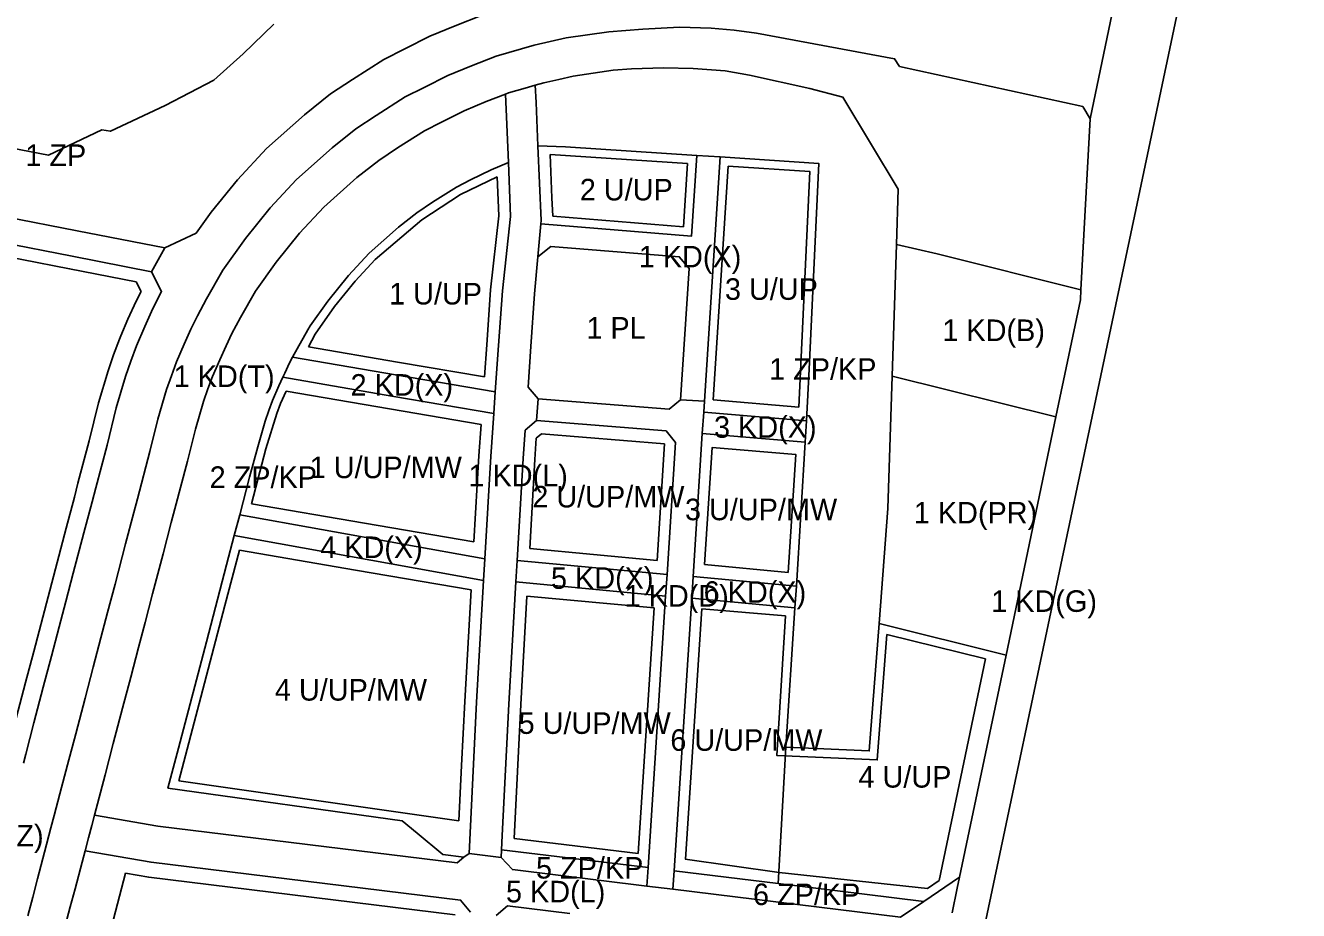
# Model space of a CAD drawing. Extents: x 7424258 to 7426021, y 5551671 to 5553193.
# Drawn here: x 7425401 to 7425992, y 5552263 to 5552673 of the extents above; entities that cross this region are included whole.
import ezdxf

# ---------------------------------------------------------------- set-up
doc = ezdxf.new("R2010")
doc.units = 0
for name, color, linetype in [('linie_rozgraniczajace', 7, 'Continuous'), ('linie_zabudowy_nieprzekraczalne', 7, 'Continuous'), ('linie_zabudowy_obowiazujace', 7, 'Continuous'), ('oznaczenia_przeznaczen', 7, 'Continuous')]:
    doc.layers.add(name, color=color, linetype=linetype)

msp = doc.modelspace()

# ---------------------------------------------------------------- linework, layer by layer
at = {"layer": 'linie_rozgraniczajace'}
for points in [[(7425991.56, 5552946.2), (7425916.04, 5552588.04), (7425881.23, 5552423.32), (7425846.58, 5552258.58)], [(7425516.29, 5552674.09), (7425501.98, 5552660.41), (7425488.46, 5552648.19), (7425465.82, 5552636.34), (7425440.5, 5552624.42), (7425436.43, 5552625.15), (7425411.75, 5552613.27), (7425339.38, 5552627.28), (7425321.43, 5552647.09), (7425251.22, 5552724.52)], [(7425906.69, 5552686.84), (7425894.92, 5552630.26), (7425891.45, 5552635.89), (7425806.54, 5552654.5), (7425804.19, 5552658.05), (7425740.11, 5552669.93), (7425729.85, 5552671.28), (7425719.09, 5552672.17), (7425704.44, 5552672.69), (7425687.35, 5552671.82), (7425671.67, 5552670.61), (7425651.9, 5552667.68), (7425637.06, 5552664.4), (7425619.34, 5552659.27), (7425608.01, 5552654.84), (7425597.01, 5552650.26), (7425585.94, 5552644.72), (7425577.21, 5552640.33), (7425563.73, 5552631.74), (7425554.37, 5552625.51), (7425543.27, 5552616.76), (7425526.81, 5552602.12), (7425514.58, 5552588.87), (7425503.09, 5552574.71), (7425492.57, 5552560.02), (7425485.04, 5552546.67), (7425480.8, 5552538.84), (7425477.8, 5552532.56), (7425474.68, 5552525.73), (7425471.14, 5552517.42), (7425468.75, 5552511.05), (7425466.52, 5552504.57), (7425462.5, 5552490.93), (7425458.73, 5552475.88), (7425452.97, 5552453.86), (7425451.31, 5552447.53), (7425447.5, 5552433.03), (7425442.6, 5552414.41), (7425439.13, 5552401.23), (7425436.07, 5552389.53), (7425432.46, 5552375.83), (7425428.69, 5552361.48), (7425424.36, 5552345.01), (7425420.55, 5552330.49), (7425417.03, 5552317.12), (7425414.37, 5552306.98), (7425412.86, 5552301.29), (7425409.89, 5552289.99), (7425406.66, 5552277.68), (7425404.45, 5552269.24), (7425402.13, 5552260.45)], [(7425830.86, 5552261.88), (7425833.28, 5552273.38), (7425834.35, 5552278.52), (7425855.89, 5552381.38), (7425879.03, 5552491.92), (7425890.41, 5552546.24), (7425890.65, 5552550.86), (7425894.92, 5552630.26), (7425906.69, 5552686.84)], [(7425612.91, 5552678.24), (7425600.34, 5552673.3), (7425588.67, 5552668.46), (7425576.97, 5552662.59), (7425567.32, 5552657.74), (7425552.82, 5552648.5), (7425542.61, 5552641.71), (7425530.42, 5552632.09), (7425512.79, 5552616.41), (7425499.46, 5552601.97), (7425487.18, 5552586.84), (7425480.2, 5552577.11), (7425465.64, 5552570.34), (7425424.98, 5552578.29), (7425358.36, 5552591.28), (7425306.08, 5552601.31), (7425191.3, 5552623.7), (7425147.23, 5552632.41), (7425138.81, 5552645.48), (7425140.06, 5552650.56), (7425144.04, 5552663.41), (7425151.8, 5552674.07)], [(7425157.19, 5552680.03), (7425250.04, 5552661.6), (7425301.71, 5552651.12), (7425321.43, 5552647.09), (7425339.38, 5552627.28), (7425411.75, 5552613.27), (7425436.43, 5552625.15), (7425440.5, 5552624.42), (7425465.82, 5552636.34), (7425488.46, 5552648.19), (7425501.98, 5552660.41), (7425516.29, 5552674.09)], [(7425499.46, 5552601.97), (7425512.79, 5552616.41), (7425530.42, 5552632.09), (7425542.61, 5552641.71), (7425552.82, 5552648.5), (7425567.32, 5552657.74), (7425576.97, 5552662.59), (7425588.67, 5552668.46), (7425600.34, 5552673.3), (7425612.91, 5552678.24)], [(7425402.13, 5552260.45), (7425404.45, 5552269.24), (7425406.66, 5552277.68), (7425409.89, 5552289.99), (7425412.86, 5552301.29), (7425414.37, 5552306.98), (7425417.03, 5552317.12), (7425420.55, 5552330.49), (7425424.36, 5552345.01), (7425428.69, 5552361.48), (7425432.46, 5552375.83), (7425436.07, 5552389.53), (7425439.13, 5552401.23), (7425442.6, 5552414.41), (7425447.5, 5552433.03), (7425451.31, 5552447.53), (7425452.97, 5552453.86), (7425458.73, 5552475.88), (7425462.5, 5552490.93), (7425466.52, 5552504.57), (7425468.75, 5552511.05), (7425471.14, 5552517.42), (7425474.68, 5552525.73), (7425477.8, 5552532.56), (7425480.8, 5552538.84), (7425485.04, 5552546.67), (7425492.57, 5552560.02), (7425503.09, 5552574.71), (7425514.58, 5552588.87), (7425526.81, 5552602.12), (7425543.27, 5552616.76), (7425554.37, 5552625.51), (7425563.73, 5552631.74), (7425577.21, 5552640.33), (7425585.94, 5552644.72), (7425597.01, 5552650.26), (7425608.01, 5552654.84), (7425619.34, 5552659.27), (7425637.06, 5552664.4), (7425651.9, 5552667.68), (7425671.67, 5552670.61), (7425687.35, 5552671.82), (7425704.44, 5552672.69), (7425719.09, 5552672.17), (7425729.85, 5552671.28), (7425740.11, 5552669.93), (7425804.19, 5552658.05), (7425806.54, 5552654.5), (7425891.45, 5552635.89), (7425894.92, 5552630.26), (7425890.65, 5552550.86), (7425823.92, 5552567.51), (7425805.06, 5552571.87), (7425805.89, 5552597.52), (7425780.24, 5552640.21), (7425764.95, 5552644.18), (7425736.94, 5552650.37), (7425725.59, 5552652.38), (7425710.7, 5552653.54), (7425696.94, 5552653.88), (7425682.2, 5552653.37), (7425673.69, 5552652.71), (7425655.16, 5552649.97), (7425648.41, 5552648.47), (7425641.51, 5552646.94), (7425637.55, 5552645.8), (7425632.85, 5552644.45), (7425625.13, 5552642.22), (7425623.71, 5552641.66), (7425614.75, 5552638.15), (7425604.51, 5552633.89), (7425594.01, 5552628.62), (7425586.11, 5552624.66), (7425573.55, 5552616.66), (7425564.95, 5552610.93)], [(7425564.95, 5552610.93), (7425554.83, 5552602.96), (7425539.44, 5552589.26), (7425528.2, 5552577.09), (7425517.4, 5552563.78), (7425507.76, 5552550.33), (7425500.8, 5552537.98), (7425496.84, 5552530.66), (7425494.11, 5552524.95), (7425491.15, 5552518.46), (7425487.85, 5552510.72), (7425485.69, 5552504.97), (7425483.68, 5552499.1), (7425479.87, 5552486.2), (7425476.17, 5552471.42), (7425470.38, 5552449.29), (7425468.71, 5552442.95), (7425464.9, 5552428.47), (7425460.01, 5552409.83), (7425456.54, 5552396.65), (7425453.46, 5552384.96), (7425449.87, 5552371.26), (7425446.1, 5552356.91), (7425441.77, 5552340.43), (7425437.96, 5552325.92), (7425433.05, 5552307.27), (7425431.77, 5552302.42), (7425430.27, 5552296.71), (7425428.7, 5552290.74), (7425427.3, 5552285.41), (7425424.07, 5552273.1), (7425421.85, 5552264.67), (7425419.54, 5552255.88)], [(7425400.09, 5552331.38), (7425401.21, 5552335.58), (7425405.02, 5552350.1), (7425409.35, 5552366.57), (7425413.12, 5552380.92), (7425416.71, 5552394.62), (7425419.79, 5552406.31), (7425423.26, 5552419.5), (7425428.15, 5552438.12), (7425431.96, 5552452.61), (7425433.64, 5552458.98), (7425438.91, 5552478.79), (7425443.21, 5552496.2), (7425447.47, 5552510.65), (7425449.93, 5552517.8), (7425452.57, 5552524.86), (7425456.39, 5552533.8), (7425460.2, 5552542.16), (7425464.18, 5552550.15), (7425459.57, 5552559.28), (7425465.64, 5552570.34), (7425480.2, 5552577.11), (7425487.18, 5552586.84), (7425499.46, 5552601.97)], [(7425356.08, 5552579.5), (7425422.69, 5552566.52), (7425459.57, 5552559.28), (7425464.18, 5552550.15), (7425460.2, 5552542.16), (7425456.39, 5552533.8), (7425452.57, 5552524.86), (7425449.93, 5552517.8), (7425447.47, 5552510.65), (7425443.21, 5552496.2), (7425438.91, 5552478.79), (7425433.64, 5552458.98), (7425431.96, 5552452.61), (7425428.15, 5552438.12), (7425423.26, 5552419.5), (7425419.79, 5552406.31), (7425416.71, 5552394.62), (7425413.12, 5552380.92), (7425409.35, 5552366.57), (7425405.02, 5552350.1), (7425401.21, 5552335.58), (7425400.09, 5552331.38)], [(7425607.51, 5552262.2), (7425602.87, 5552267.8), (7425459.3, 5552285.38), (7425428.7, 5552290.74), (7425430.27, 5552296.71), (7425431.77, 5552302.42), (7425433.05, 5552307.27), (7425462.51, 5552302.11), (7425601.24, 5552285.12), (7425604.38, 5552287.76), (7425606.81, 5552289.46), (7425621.74, 5552287.61), (7425626.92, 5552281.98), (7425689.34, 5552274.33), (7425701.37, 5552272.89), (7425807, 5552259.94), (7425817.72, 5552267.22), (7425834.35, 5552278.52), (7425833.28, 5552273.38), (7425830.86, 5552261.88)], [(7425419.54, 5552255.88), (7425421.85, 5552264.67), (7425424.07, 5552273.1), (7425427.3, 5552285.41), (7425428.7, 5552290.74), (7425459.3, 5552285.38), (7425602.87, 5552267.8), (7425607.51, 5552262.2)], [(7425653.53, 5552261.6), (7425624.71, 5552265.13), (7425619.43, 5552260.74)], [(7425619.43, 5552260.74), (7425624.71, 5552265.13), (7425653.53, 5552261.6)]]:
    msp.add_lwpolyline(points, dxfattribs=at)
for points in [[(7425637.55, 5552645.8), (7425641.51, 5552646.94), (7425648.41, 5552648.47), (7425655.16, 5552649.97), (7425673.69, 5552652.71), (7425682.2, 5552653.37), (7425696.94, 5552653.88), (7425710.7, 5552653.54), (7425725.59, 5552652.38), (7425736.94, 5552650.37), (7425764.95, 5552644.18), (7425780.24, 5552640.21), (7425805.89, 5552597.52), (7425805.06, 5552571.87), (7425803.09, 5552510.87), (7425801.1, 5552449.52), (7425796.99, 5552396.12), (7425792.46, 5552337.02), (7425753.75, 5552338.72), (7425757.99, 5552403.38), (7425758.63, 5552413.36), (7425762.75, 5552480.15), (7425763.39, 5552490.13), (7425764.56, 5552514.06), (7425769.03, 5552609.51), (7425723.34, 5552612.53), (7425712.42, 5552613.24), (7425651.59, 5552617.25), (7425638.73, 5552617.67), (7425637.89, 5552637.73)], [(7425606.81, 5552289.46), (7425610.31, 5552359.58), (7425613.57, 5552416.04), (7425614.14, 5552426.1), (7425616.87, 5552473.55), (7425618.27, 5552493.51), (7425618.98, 5552503.54), (7425620.5, 5552524.98), (7425622.28, 5552550.34), (7425626.1, 5552584.96), (7425625.04, 5552609.95), (7425623.71, 5552641.66), (7425625.13, 5552642.22), (7425632.85, 5552644.45), (7425637.55, 5552645.8), (7425637.89, 5552637.73), (7425638.73, 5552617.67), (7425640.19, 5552582.98), (7425640.06, 5552581.44), (7425638.72, 5552566.12), (7425637.22, 5552548.98), (7425635.49, 5552524.54), (7425634.16, 5552505.67), (7425638.88, 5552500.26), (7425638.07, 5552490.24), (7425632.78, 5552485.71), (7425631.84, 5552472.59), (7425629.12, 5552425.38), (7425628.55, 5552415.37), (7425625.3, 5552358.77), (7425622.25, 5552297.85), (7425621.92, 5552291.19), (7425621.74, 5552287.61)], [(7425433.05, 5552307.27), (7425437.96, 5552325.92), (7425441.77, 5552340.43), (7425446.1, 5552356.91), (7425449.87, 5552371.26), (7425453.46, 5552384.96), (7425456.54, 5552396.65), (7425460.01, 5552409.83), (7425464.9, 5552428.47), (7425468.71, 5552442.95), (7425470.38, 5552449.29), (7425476.17, 5552471.42), (7425479.87, 5552486.2), (7425483.68, 5552499.1), (7425485.69, 5552504.97), (7425487.85, 5552510.72), (7425491.15, 5552518.46), (7425494.11, 5552524.95), (7425496.84, 5552530.66), (7425500.8, 5552537.98), (7425507.76, 5552550.33), (7425517.4, 5552563.78), (7425528.2, 5552577.09), (7425539.44, 5552589.26), (7425554.83, 5552602.96), (7425564.95, 5552610.93), (7425573.55, 5552616.66), (7425586.11, 5552624.66), (7425594.01, 5552628.62), (7425604.51, 5552633.89), (7425614.75, 5552638.15), (7425623.71, 5552641.66), (7425625.04, 5552609.95), (7425617.01, 5552606.6), (7425607.47, 5552601.82), (7425600.94, 5552598.53), (7425589.92, 5552591.52), (7425582.57, 5552586.63), (7425574.1, 5552579.95), (7425560.47, 5552567.83), (7425550.9, 5552557.45), (7425541.26, 5552545.58), (7425533.1, 5552534.18), (7425532.02, 5552532.27), (7425527.05, 5552523.47), (7425524.99, 5552519.64), (7425523.58, 5552517.04), (7425521.29, 5552512.27), (7425520.39, 5552510.29), (7425518.6, 5552506.34), (7425515.71, 5552499.56), (7425513.94, 5552494.84), (7425512.26, 5552489.98), (7425508.77, 5552478.13), (7425505.03, 5552463.91), (7425500.47, 5552446.57), (7425497.92, 5552436.87), (7425494.36, 5552423.31), (7425484.98, 5552387.62), (7425471.99, 5552338.21), (7425467.15, 5552319.77), (7425575.74, 5552304.54), (7425582.75, 5552298.81), (7425594.63, 5552288.96), (7425604.38, 5552287.76), (7425601.24, 5552285.12), (7425462.51, 5552302.11)], [(7425144.37, 5552620.75), (7425147.23, 5552632.41), (7425191.3, 5552623.7), (7425306.08, 5552601.31), (7425358.36, 5552591.28), (7425424.98, 5552578.29), (7425465.64, 5552570.34), (7425459.57, 5552559.28), (7425422.69, 5552566.52), (7425356.08, 5552579.5), (7425303.8, 5552589.54), (7425262.75, 5552597.67), (7425257.06, 5552593.76), (7425212.18, 5552352.94), (7425209.14, 5552336.67), (7425199.16, 5552337.71), (7425202.26, 5552354.34), (7425227.54, 5552489.91), (7425247.19, 5552595.37), (7425243.07, 5552601.38), (7425188.99, 5552611.93)], [(7425638.72, 5552566.12), (7425640.06, 5552581.44), (7425709.93, 5552575.76), (7425712.42, 5552613.24), (7425723.34, 5552612.53), (7425715.98, 5552499.18), (7425704.9, 5552499.9), (7425708.94, 5552560.8), (7425704.29, 5552566.19), (7425644.68, 5552571.03)], [(7425640.06, 5552581.44), (7425640.19, 5552582.98), (7425638.73, 5552617.67), (7425651.59, 5552617.25), (7425712.42, 5552613.24), (7425709.93, 5552575.76)], [(7425715.66, 5552494.18), (7425715.98, 5552499.18), (7425723.34, 5552612.53), (7425769.03, 5552609.51), (7425764.56, 5552514.06), (7425763.39, 5552490.13)], [(7425524.99, 5552519.64), (7425527.05, 5552523.47), (7425532.02, 5552532.27), (7425533.1, 5552534.18), (7425541.26, 5552545.58), (7425550.9, 5552557.45), (7425560.47, 5552567.83), (7425574.1, 5552579.95), (7425582.57, 5552586.63), (7425589.92, 5552591.52), (7425600.94, 5552598.53), (7425607.47, 5552601.82), (7425617.01, 5552606.6), (7425625.04, 5552609.95), (7425626.1, 5552584.96), (7425622.28, 5552550.34), (7425620.5, 5552524.98), (7425618.98, 5552503.54), (7425572.69, 5552511.4)], [(7425638.88, 5552500.26), (7425634.16, 5552505.67), (7425635.49, 5552524.54), (7425637.22, 5552548.98), (7425638.72, 5552566.12), (7425644.68, 5552571.03), (7425704.29, 5552566.19), (7425708.94, 5552560.8), (7425704.9, 5552499.9), (7425699.59, 5552495.45)], [(7425803.09, 5552510.87), (7425805.06, 5552571.87), (7425823.92, 5552567.51), (7425890.65, 5552550.86), (7425890.41, 5552546.24), (7425879.03, 5552491.92)], [(7425520.39, 5552510.29), (7425521.29, 5552512.27), (7425523.58, 5552517.04), (7425524.99, 5552519.64), (7425572.69, 5552511.4), (7425618.98, 5552503.54), (7425618.27, 5552493.51), (7425571, 5552501.54)], [(7425500.47, 5552446.57), (7425505.03, 5552463.91), (7425508.77, 5552478.13), (7425512.26, 5552489.98), (7425513.94, 5552494.84), (7425515.71, 5552499.56), (7425518.6, 5552506.34), (7425520.39, 5552510.29), (7425571, 5552501.54), (7425618.27, 5552493.51), (7425616.87, 5552473.55), (7425614.14, 5552426.1)], [(7425796.99, 5552396.12), (7425801.1, 5552449.52), (7425803.09, 5552510.87), (7425879.03, 5552491.92), (7425855.89, 5552381.38)], [(7425638.07, 5552490.24), (7425638.88, 5552500.26), (7425699.59, 5552495.45), (7425704.9, 5552499.9), (7425715.98, 5552499.18), (7425715.66, 5552494.18), (7425715, 5552484.19), (7425710.81, 5552417.87), (7425710.15, 5552407.88), (7425701.91, 5552281.4), (7425701.37, 5552272.89), (7425689.34, 5552274.33), (7425689.89, 5552282.87), (7425698.01, 5552408.83), (7425698.66, 5552418.82), (7425702.6, 5552480.02), (7425698.19, 5552485.4)], [(7425715, 5552484.19), (7425715.66, 5552494.18), (7425763.39, 5552490.13), (7425762.75, 5552480.15)], [(7425629.12, 5552425.38), (7425631.84, 5552472.59), (7425632.78, 5552485.71), (7425638.07, 5552490.24), (7425698.19, 5552485.4), (7425702.6, 5552480.02), (7425698.66, 5552418.82)], [(7425710.81, 5552417.87), (7425715, 5552484.19), (7425762.75, 5552480.15), (7425758.63, 5552413.36)], [(7425497.92, 5552436.87), (7425500.47, 5552446.57), (7425614.14, 5552426.1), (7425613.57, 5552416.04)], [(7425497.92, 5552436.87), (7425613.57, 5552416.04), (7425610.31, 5552359.58), (7425606.81, 5552289.46), (7425604.38, 5552287.76), (7425594.63, 5552288.96), (7425582.75, 5552298.81), (7425575.74, 5552304.54), (7425467.15, 5552319.77), (7425471.99, 5552338.21), (7425484.98, 5552387.62), (7425494.36, 5552423.31)], [(7425628.55, 5552415.37), (7425629.12, 5552425.38), (7425698.66, 5552418.82), (7425698.01, 5552408.83)], [(7425710.15, 5552407.88), (7425710.81, 5552417.87), (7425758.63, 5552413.36), (7425757.99, 5552403.38)], [(7425621.92, 5552291.19), (7425622.25, 5552297.85), (7425625.3, 5552358.77), (7425628.55, 5552415.37), (7425698.01, 5552408.83), (7425689.89, 5552282.87)], [(7425701.91, 5552281.4), (7425710.15, 5552407.88), (7425757.99, 5552403.38), (7425753.75, 5552338.72), (7425750.16, 5552275.48)], [(7425750.16, 5552275.48), (7425753.75, 5552338.72), (7425792.46, 5552337.02), (7425796.99, 5552396.12), (7425855.89, 5552381.38), (7425834.35, 5552278.52), (7425817.72, 5552267.22)], [(7425621.74, 5552287.61), (7425621.92, 5552291.19), (7425689.89, 5552282.87), (7425689.34, 5552274.33), (7425626.92, 5552281.98)], [(7425701.37, 5552272.89), (7425701.91, 5552281.4), (7425750.16, 5552275.48), (7425817.72, 5552267.22), (7425807, 5552259.94)]]:
    msp.add_lwpolyline(points, close=True, dxfattribs=at)
at = {"layer": 'linie_zabudowy_nieprzekraczalne'}
for points in [[(7425644.4, 5552613.72), (7425708.17, 5552609.51)], [(7425727.07, 5552608.27), (7425764.85, 5552605.77), (7425759.73, 5552496.47)], [(7425532.27, 5552524.47), (7425535.5, 5552530.3), (7425544.45, 5552543.15), (7425553.92, 5552554.83), (7425563.28, 5552564.97), (7425584.92, 5552583.38), (7425602.91, 5552595.05), (7425619.82, 5552603.24)], [(7425452.42, 5552554.59), (7425421.53, 5552560.63), (7425354.94, 5552573.61), (7425302.66, 5552583.64), (7425263.93, 5552591.2)], [(7425452.42, 5552554.59), (7425454.68, 5552550.13)], [(7425392.58, 5552336.23), (7425396.8, 5552352.26), (7425401.12, 5552368.72), (7425404.9, 5552383.08), (7425411.57, 5552408.47), (7425419.93, 5552440.28), (7425423.74, 5552454.77), (7425425.42, 5552461.15), (7425430.68, 5552480.9), (7425435, 5552498.41), (7425439.37, 5552513.23), (7425441.92, 5552520.67), (7425444.67, 5552528.02), (7425445.35, 5552529.6), (7425448.62, 5552537.24), (7425452.46, 5552545.68), (7425454.68, 5552550.13)], [(7425505.95, 5552451.69), (7425508.9, 5552462.89), (7425512.62, 5552477.06), (7425517.7, 5552493.49), (7425519.42, 5552498.08), (7425522.05, 5552503.92)], [(7425522.05, 5552503.92), (7425569.99, 5552495.63), (7425612.4, 5552488.43)], [(7425609.09, 5552434.02), (7425611.38, 5552473.9), (7425612.4, 5552488.43)], [(7425640.39, 5552484.08), (7425638.01, 5552482.04), (7425637.32, 5552472.24), (7425634.94, 5552430.84)], [(7425694.05, 5552425.28), (7425697.54, 5552479.43)], [(7425716.07, 5552423.4), (7425719.61, 5552477.79), (7425758.38, 5552474.5), (7425754.9, 5552419.74)], [(7425505.95, 5552451.69), (7425558.32, 5552442.64), (7425609.09, 5552434.02)], [(7425472.16, 5552323.1), (7425482.35, 5552361.9), (7425493.54, 5552404.44), (7425500.31, 5552430.2)], [(7425500.31, 5552430.2), (7425554.22, 5552420.88), (7425607.81, 5552411.78)], [(7425634.94, 5552430.84), (7425694.05, 5552425.28)], [(7425716.07, 5552423.4), (7425754.9, 5552419.74)], [(7425602.07, 5552304.62), (7425603.35, 5552330.24), (7425604.83, 5552359.87), (7425607.81, 5552411.78)], [(7425633.67, 5552408.86), (7425630.79, 5552358.48), (7425627.69, 5552296.42)], [(7425633.67, 5552408.86), (7425692.64, 5552403.31)], [(7425685.31, 5552289.47), (7425692.64, 5552403.31)], [(7425707.2, 5552286.79), (7425714.74, 5552402.84)], [(7425714.74, 5552402.84), (7425753.62, 5552399.68)], [(7425753.62, 5552399.68), (7425749.5, 5552334.9), (7425796.15, 5552332.85), (7425800.62, 5552391.08)], [(7425800.62, 5552391.08), (7425846.33, 5552379.65)], [(7425846.33, 5552379.65), (7425824.81, 5552276.88)], [(7425472.16, 5552323.1), (7425602.07, 5552304.62)], [(7425627.69, 5552296.42), (7425685.31, 5552289.47)], [(7425707.04, 5552286.81), (7425750.6, 5552280.61), (7425819.48, 5552273.25)], [(7425447.48, 5552280.34), (7425440.92, 5552255.39), (7425431.06, 5552217.89), (7425424.52, 5552194.47), (7425404.81, 5552118.16)], [(7425447.48, 5552280.34), (7425458.26, 5552278.45), (7425600.41, 5552261.05)], [(7425819.48, 5552273.25), (7425824.81, 5552276.88)]]:
    msp.add_lwpolyline(points, dxfattribs=at)
at = {"layer": 'linie_zabudowy_obowiazujace'}
for points in [[(7425645.61, 5552585.01), (7425645.25, 5552593.52), (7425644.4, 5552613.72)], [(7425706.21, 5552580.08), (7425708.17, 5552609.51)], [(7425720.03, 5552499.83), (7425727.07, 5552608.27)], [(7425613.96, 5552510.48), (7425615.01, 5552525.37), (7425616.8, 5552550.83), (7425620.58, 5552585.15), (7425619.82, 5552603.24)], [(7425706.21, 5552580.08), (7425645.61, 5552585.01)], [(7425532.27, 5552524.47), (7425573.7, 5552517.31), (7425613.96, 5552510.48)], [(7425720.03, 5552499.83), (7425759.73, 5552496.47)], [(7425640.39, 5552484.08), (7425697.54, 5552479.43)]]:
    msp.add_lwpolyline(points, dxfattribs=at)

# ---------------------------------------------------------------- texts
at = {"layer": 'oznaczenia_przeznaczen'}
for s, p in [('1 ZP', (7425401.01, 5552608.32)), ('2 U/UP', (7425658.19, 5552592.35)), ('1 KD(X)', (7425685.54, 5552561.27)), ('1 U/UP', (7425569.72, 5552544.07)), ('3 U/UP', (7425725.51, 5552546.22)), ('1 PL', (7425661.25, 5552528.24)), ('1 KD(B)', (7425826.36, 5552527.12)), ('1 ZP/KP', (7425746, 5552509.14)), ('1 KD(T)', (7425469.82, 5552505.8)), ('2 KD(X)', (7425551.86, 5552501.77)), ('3 KD(X)', (7425720.45, 5552482.25)), ('1 U/UP/MW', (7425532.91, 5552463.53)), ('2 ZP/KP', (7425486.48, 5552458.99)), ('1 KD(L)', (7425606.55, 5552459.76)), ('2 U/UP/MW', (7425636.15, 5552449.95)), ('3 U/UP/MW', (7425706.98, 5552444.01)), ('1 KD(PR)', (7425813.12, 5552442.5)), ('4 KD(X)', (7425537.78, 5552426.47)), ('5 KD(X)', (7425644.82, 5552412.19)), ('1 KD(D)', (7425678.98, 5552403.92)), ('6 KD(X)', (7425715.64, 5552405.7)), ('1 KD(G)', (7425849.01, 5552401.5)), ('4 U/UP/MW', (7425516.75, 5552360.35)), ('5 U/UP/MW', (7425629.8, 5552344.91)), ('6 U/UP/MW', (7425700.18, 5552337.06)), ('4 U/UP', (7425787.45, 5552320)), ('1 KD(Z)', (7425362.69, 5552292.72)), ('5 ZP/KP', (7425637.88, 5552277.81)), ('5 KD(L)', (7425623.95, 5552266.76)), ('6 ZP/KP', (7425738.51, 5552265.5))]:
    msp.add_text(s, height=10, dxfattribs=at).set_placement(p)

doc.saveas('drawing.dxf')
